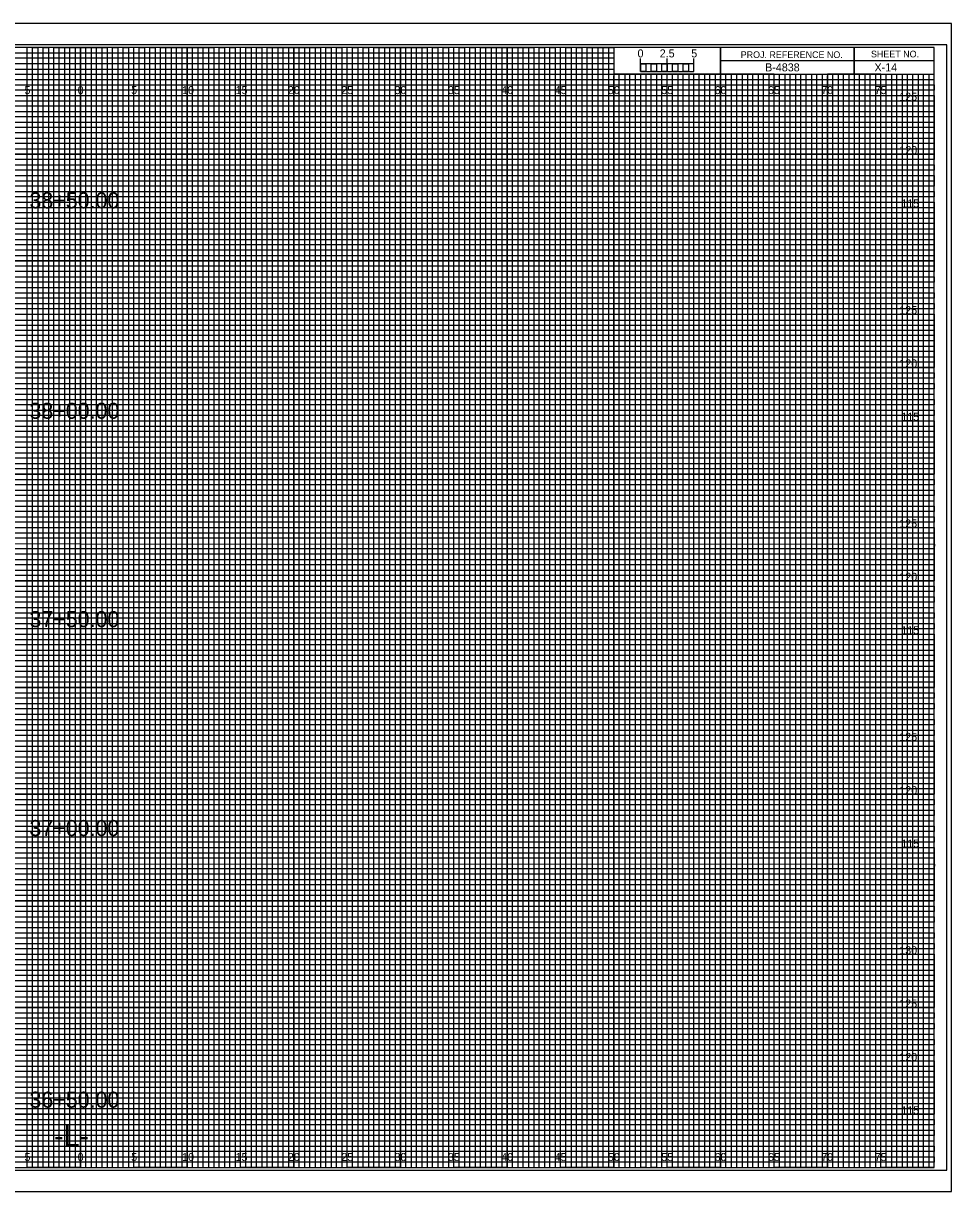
# Model space of a CAD drawing. Extents: x -7 to 182, y -2 to 1647.
# Drawn here: x 74.6 to 161.7, y 1317.8 to 1427.2 of the extents above; entities that cross this region are included whole.
import ezdxf

# ---------------------------------------------------------------- set-up
doc = ezdxf.new("R2010")
doc.units = 0
for name, color, linetype in [('Exist CMT Pavement', 7, 'Continuous'), ('Exist Cross Section Cell', 7, 'Continuous'), ('Exist XS Ground Line', 7, 'Continuous'), ('Prop CMT Pvmt Course 1', 7, 'Continuous'), ('Prop CMT Pvmt Course 2', 7, 'Continuous'), ('Prop CMT Pvmt Course 2 Wedge', 7, 'Continuous'), ('Prop CMT Pvmt Course 3', 7, 'Continuous'), ('Prop CMT Pvmt Surface', 7, 'Continuous'), ('Prop CMT Pvmt Surface Shoulder', 7, 'Continuous'), ('Prop CMT Pvmt Wedge Surface 1', 7, 'Continuous'), ('Prop CMT Pvmt Wedge Surface 2', 7, 'Continuous'), ('Prop CMT Pvmt Wedge Surface 3', 7, 'Continuous'), ('Prop CMT Shld Paved Course 1', 7, 'Continuous'), ('Prop CMT Shld Paved Course 2', 7, 'Continuous'), ('Prop CMT Shld Paved Course 3', 7, 'Continuous'), ('Prop CMT Slope Grass', 7, 'Continuous'), ('Prop CMT Subgrade Earthwork', 7, 'Continuous')]:
    doc.layers.add(name, color=color, linetype=linetype)

msp = doc.modelspace()

# ---------------------------------------------------------------- linework, layer by layer
at = {"layer": 'Exist XS Ground Line'}
for p, q in [((75, 1425), (70, 1425)), ((75, 1320), (75, 1425)), ((85, 1425), (80, 1425)), ((80, 1425), (80, 1320)), ((85, 1320), (85, 1425)), ((95, 1425), (90, 1425)), ((90, 1425), (90, 1320)), ((95, 1320), (95, 1425)), ((105, 1425), (100, 1425)), ((100, 1425), (100, 1320)), ((105, 1320), (105, 1425)), ((115, 1425), (110, 1425)), ((110, 1425), (110, 1320)), ((115, 1320), (115, 1425)), ((125, 1425), (120, 1425)), ((120, 1425), (120, 1320)), ((125, 1320), (125, 1425)), ((130, 1425), (130, 1320)), ((135, 1320), (135, 1422.5)), ((145, 1422.5), (140, 1422.5)), ((140, 1422.5), (140, 1320)), ((145, 1320), (145, 1422.5)), ((155, 1422.5), (150, 1422.5)), ((150, 1422.5), (150, 1320)), ((155, 1320), (155, 1422.5)), ((80, 1320), (75, 1320)), ((90, 1320), (85, 1320)), ((100, 1320), (95, 1320)), ((110, 1320), (105, 1320)), ((120, 1320), (115, 1320)), ((130, 1320), (125, 1320)), ((140, 1320), (135, 1320)), ((150, 1320), (145, 1320)), ((160, 1320), (155, 1320)), ((160, 1320), (160, 1320))]:
    msp.add_line(p, q, dxfattribs=at)
for points in [[(0, 1420), (160, 1420), (160, 1415), (0, 1415)], [(0, 1410), (160, 1410), (160, 1405), (0, 1405)], [(0, 1400), (160, 1400), (160, 1395), (0, 1395)], [(0, 1390), (160, 1390), (160, 1385), (0, 1385)], [(0, 1380), (160, 1380), (160, 1375), (0, 1375)], [(0, 1370), (160, 1370), (160, 1365), (0, 1365)], [(0, 1360), (160, 1360), (160, 1355), (0, 1355)], [(0, 1350), (160, 1350), (160, 1345), (0, 1345)], [(0, 1340), (160, 1340), (160, 1335), (0, 1335)], [(0, 1330), (160, 1330), (160, 1325), (0, 1325)]]:
    msp.add_lwpolyline(points, dxfattribs=at)
at = {"layer": 'Prop CMT Pvmt Course 2'}
for p, q in [((132.5, 1422.75), (132.5, 1423.95)), ((132.5, 1423.45), (132.5, 1423.95)), ((135, 1422.75), (135, 1423.95)), ((137.5, 1422.75), (137.5, 1423.95)), ((137.5, 1423.45), (137.5, 1423.95))]:
    msp.add_line(p, q, dxfattribs=at)
for points in [[(137.5, 1423.45), (132.5, 1423.45), (132.5, 1422.75), (137.5, 1422.75)], [(132.5, 1423.45), (133, 1423.45), (133, 1422.75), (132.5, 1422.75)], [(133.5, 1423.45), (134, 1423.45), (134, 1422.75), (133.5, 1422.75)], [(134.5, 1423.45), (135, 1423.45), (135, 1422.75), (134.5, 1422.75)], [(135.5, 1423.45), (136, 1423.45), (136, 1422.75), (135.5, 1422.75)], [(136.5, 1423.45), (137, 1423.45), (137, 1422.75), (136.5, 1422.75)]]:
    msp.add_lwpolyline(points, close=True, dxfattribs=at)
at = {"layer": 'Prop CMT Pvmt Course 3'}
msp.add_lwpolyline([(-6.7, 1317.75), (161.65, 1317.75), (161.65, 1427.25), (-6.7, 1427.25)], close=True, dxfattribs=at)
at = {"layer": 'Prop CMT Pvmt Wedge Surface 1'}
for p, q in [((0, 1424.5), (130, 1424.5)), ((130, 1423.99), (0, 1423.99)), ((0, 1423.5), (130, 1423.5)), ((130, 1424.5), (130, 1423.99)), ((130, 1423.5), (130, 1422.94)), ((130, 1422.94), (0, 1422.94)), ((0, 1422), (160, 1422))]:
    msp.add_line(p, q, dxfattribs=at)
for points in [[(0, 1421.5), (135, 1421.5), (160, 1421.5), (160, 1421), (0, 1421)], [(0, 1420.5), (160, 1420.5), (160, 1419.5), (0, 1419.5)], [(0, 1419), (160, 1419), (160, 1418.5), (0, 1418.49)], [(0, 1418), (160, 1418), (160, 1417), (0, 1417)], [(0, 1416.5), (160, 1416.5), (160, 1416), (0, 1416)], [(0, 1415.5), (160, 1415.5), (160, 1414.5), (0, 1414.5)], [(0, 1414), (160, 1414), (160, 1413.5), (0, 1413.5)], [(0, 1413), (160, 1413), (160, 1412), (0, 1412)], [(0, 1411.5), (160, 1411.5), (160, 1411), (0, 1411)], [(0, 1410.5), (160, 1410.5), (160, 1409.5), (0, 1409.5)], [(0, 1409), (160, 1409), (160, 1408.5), (0, 1408.5)], [(0, 1408), (160, 1408), (160, 1406.98), (160, 1406.5), (160, 1406), (0, 1406)], [(0, 1407), (160, 1407), (160, 1406.5), (0, 1406.5)], [(0, 1405.5), (160, 1405.5), (160, 1404.5), (0, 1404.52)], [(0, 1404.52), (160, 1404.5), (160, 1404), (0, 1404)], [(0, 1403.5), (160, 1403.5), (160, 1403), (0, 1403)], [(0, 1402), (160, 1402), (160, 1401.5), (0, 1401.5)], [(0, 1401), (160, 1401), (160, 1400.5), (0, 1400.5)], [(-0.04, 1399.44), (160, 1399.44), (160, 1398.94), (-0.04, 1398.94)], [(0, 1398.5), (160, 1398.5), (160, 1398), (0, 1398)], [(0, 1397), (160, 1397), (160, 1396.5), (0, 1396.5)], [(0, 1396), (160, 1396), (160, 1395.5), (0, 1395.5)], [(0, 1394.5), (160, 1394.5), (160, 1394), (0, 1394)], [(0, 1393.5), (160, 1393.5), (160, 1393), (0, 1393)], [(0, 1392), (160, 1392), (160, 1391.5), (0, 1391.5)], [(0, 1391), (160, 1391), (160, 1390.5), (0, 1390.5)], [(0, 1389.5), (160, 1389.5), (160, 1388.99), (0, 1389)], [(0, 1388.5), (160, 1388.5), (160, 1388), (0, 1388)], [(0, 1387), (160, 1387), (160, 1386.5), (0, 1386.5)], [(0, 1386), (160, 1386), (160, 1385.5), (0, 1385.5)], [(0, 1384.5), (160, 1384.5), (160, 1384), (0, 1384)], [(0, 1383.5), (160, 1383.5), (160, 1383), (0, 1383)], [(0, 1382), (160, 1382), (160, 1381.5), (0, 1381.5)], [(0, 1381), (160, 1381), (160, 1380.5), (0, 1380.5)], [(0, 1379.5), (160, 1379.5), (160, 1379), (0, 1379)], [(0, 1378.5), (160.03, 1378.45), (160, 1378), (0, 1378)], [(0, 1377), (160, 1377), (160, 1376.5), (0, 1376.5)], [(0, 1376), (160, 1376), (160, 1375.5), (0, 1375.5)], [(0, 1374.5), (160, 1374.5), (160, 1374), (0, 1374)], [(0, 1373.5), (160, 1373.5), (160, 1373), (0, 1373)], [(0, 1372), (160, 1372), (160, 1371.5), (0, 1371.5)], [(0, 1371), (160, 1371), (160, 1370.5), (0, 1370.5)], [(0, 1369.5), (160, 1369.5), (160, 1369), (0, 1369)], [(0, 1368.5), (160, 1368.5), (160, 1368), (0, 1368)], [(0, 1367), (160, 1367), (160, 1366.5), (0, 1366.5)], [(0, 1366), (160, 1366), (160, 1365.5), (0, 1365.5)], [(0, 1364.5), (160, 1364.5), (160, 1364), (0, 1364)], [(0, 1363.5), (160, 1363.5), (160, 1363), (0, 1363)], [(0, 1362), (160, 1362), (160, 1361.5), (0, 1361.5)], [(0, 1361), (160, 1361), (160, 1360.5), (0, 1360.5)], [(0, 1359.5), (160, 1359.5), (160, 1358.99), (0, 1359)], [(0, 1358.5), (160, 1358.5), (160, 1358), (0, 1358)], [(0, 1357), (160, 1357), (160, 1356.5), (0, 1356.5)], [(0, 1356), (160, 1356), (160, 1355.5), (0, 1355.5)], [(0, 1354.5), (160, 1354.5), (160, 1354), (0, 1354)], [(0, 1353.5), (160, 1353.5), (160, 1353), (0, 1353)], [(0, 1352), (160, 1352), (160, 1351.5), (0, 1351.5)], [(0, 1351), (160, 1351), (160, 1350.5), (0, 1350.5)], [(0, 1349.5), (160, 1349.5), (160, 1349), (0, 1349)], [(0, 1348.5), (160.03, 1348.45), (160, 1348), (0, 1348)], [(0, 1347), (160, 1347), (160, 1346.5), (0, 1346.5)], [(0, 1346), (160, 1346), (160, 1345.5), (0, 1345.5)], [(0, 1344.5), (160, 1344.5), (160, 1344), (0, 1344)], [(0, 1343.5), (160, 1343.5), (160, 1343), (0, 1343)], [(0, 1342), (160, 1342), (160, 1341.5), (0, 1341.5)], [(0, 1341), (160, 1341), (160, 1340.5), (0, 1340.5)], [(0, 1339.5), (160, 1339.5), (160, 1339), (0, 1339)], [(0, 1338.5), (160, 1338.5), (160, 1338), (0, 1338)], [(0, 1337), (160, 1337), (160, 1336.5), (0, 1336.5)], [(0, 1336), (160, 1336), (160, 1335.5), (0, 1335.5)], [(0, 1334.5), (160, 1334.5), (160, 1334), (0, 1334)], [(0, 1333.5), (160, 1333.5), (160, 1333), (0, 1333)], [(0, 1332), (160, 1332), (160, 1331.5), (0, 1331.5)], [(0, 1331), (160, 1331), (160, 1330.5), (0, 1330.5)], [(0, 1329.5), (160, 1329.5), (160, 1329), (0, 1329)], [(0, 1328.5), (160, 1328.5), (160, 1328), (0, 1328)], [(0, 1327), (160, 1327), (160, 1326.5), (0, 1326.5)], [(0, 1326), (160, 1326), (160, 1325.5), (0, 1325.5)], [(0, 1324.5), (160, 1324.5), (160, 1324), (0, 1324)], [(0, 1323.5), (160, 1323.5), (160, 1323), (0, 1323)], [(0, 1322), (160, 1322), (160, 1321.5), (0, 1321.5)], [(0, 1321), (160, 1321), (160, 1320.5), (0, 1320.5)]]:
    msp.add_lwpolyline(points, dxfattribs=at)
at = {"layer": 'Prop CMT Pvmt Wedge Surface 2'}
for p, q in [((152.5, 1425), (152.5, 1422.5)), ((152.5, 1422.5), (152.5, 1425)), ((160, 1423.75), (140, 1423.75)), ((140, 1423.75), (140, 1422.5)), ((140, 1422.5), (160, 1422.5))]:
    msp.add_line(p, q, dxfattribs=at)
for points in [[(160, 1425), (0, 1425), (0, 1320), (160, 1320)], [(140, 1425), (130, 1425), (130, 1422.52), (140, 1422.52)], [(160, 1425), (140, 1425), (140, 1422.5), (160, 1422.5)]]:
    msp.add_lwpolyline(points, close=True, dxfattribs=at)
at = {"layer": 'Prop CMT Pvmt Wedge Surface 3'}
for p, q in [((133.5, 1422.5), (133, 1422.5)), ((133, 1422.5), (133, 1320)), ((133.5, 1320), (133.5, 1422.5)), ((134.5, 1422.5), (134, 1422.5)), ((134, 1422.5), (134, 1320)), ((134.5, 1320), (134.5, 1422.5)), ((133, 1320), (132.5, 1320)), ((134, 1320), (133.5, 1320))]:
    msp.add_line(p, q, dxfattribs=at)
for points in [[(75, 1320), (75.5, 1320), (75.5, 1425), (76, 1425), (76, 1320)], [(76, 1320), (76.5, 1320), (76.5, 1425), (77, 1425), (77, 1320)], [(77.5, 1320), (78, 1320), (78, 1425), (78.5, 1425), (78.5, 1320)], [(78.5, 1320), (79, 1320), (79, 1425), (79.5, 1425), (79.5, 1320)], [(80, 1320), (80.5, 1320), (80.5, 1425), (81, 1425), (81, 1320)], [(81, 1320), (81.5, 1320), (81.5, 1425), (82, 1425), (82, 1320)], [(82.5, 1320), (83, 1320), (83, 1425), (83.5, 1425), (83.5, 1320)], [(83.5, 1320), (84, 1320), (84, 1425), (84.5, 1425), (84.5, 1320)], [(85, 1320), (85.5, 1320), (85.5, 1425), (86, 1425), (86, 1320)], [(86, 1320), (86.5, 1320), (86.5, 1425), (87, 1425), (87, 1320)], [(87.5, 1320), (88, 1320), (88, 1425), (88.5, 1425), (88.5, 1320)], [(88.5, 1320), (89, 1320), (89, 1425), (89.5, 1425), (89.5, 1320)], [(90, 1320), (90.5, 1320), (90.5, 1425), (91, 1425), (91, 1320)], [(91, 1320), (91.5, 1320), (91.5, 1425), (92, 1425), (92, 1320)], [(92.5, 1320), (93, 1320), (93, 1425), (93.5, 1425), (93.5, 1320)], [(93.5, 1320), (94, 1320), (94, 1425), (94.5, 1425), (94.5, 1320)], [(95, 1320), (95.5, 1320), (95.5, 1425), (96, 1425), (96, 1320)], [(96, 1320), (96.5, 1320), (96.5, 1425), (97, 1425), (97, 1320)], [(97.5, 1320), (98, 1320), (98, 1425), (98.5, 1425), (98.5, 1320)], [(98.5, 1320), (99, 1320), (99, 1425), (99.5, 1425), (99.5, 1320)], [(100, 1320), (100.5, 1320), (100.5, 1425), (101, 1425), (101, 1320)], [(101, 1320), (101.5, 1320), (101.5, 1425), (102, 1425), (102, 1320)], [(102.5, 1320), (103, 1320), (103, 1425), (103.5, 1425), (103.5, 1320)], [(103.5, 1320), (104, 1320), (104, 1425), (104.5, 1425), (104.5, 1320)], [(105, 1320), (105.5, 1320), (105.5, 1425), (106, 1425), (106, 1320)], [(106, 1320), (106.5, 1320), (106.5, 1425), (107, 1425), (107, 1320)], [(107.5, 1320), (108, 1320), (108, 1425), (108.5, 1425), (108.5, 1320)], [(108.5, 1320), (109, 1320), (109, 1425), (109.5, 1425), (109.5, 1320)], [(110, 1320), (110.5, 1320), (110.5, 1425), (111, 1425), (111, 1320)], [(111, 1320), (111.5, 1320), (111.5, 1425), (112, 1425), (112, 1320)], [(112.5, 1320), (113, 1320), (113, 1425), (113.5, 1425), (113.5, 1320)], [(113.5, 1320), (114, 1320), (114, 1425), (114.5, 1425), (114.5, 1320)], [(115, 1320), (115.5, 1320), (115.5, 1425), (116, 1425), (116, 1320)], [(116, 1320), (116.5, 1320), (116.5, 1425), (117, 1425), (117, 1320)], [(117.5, 1320), (118, 1320), (118, 1425), (118.5, 1425), (118.5, 1320)], [(118.5, 1320), (119, 1320), (119, 1425), (119.5, 1425), (119.5, 1320)], [(120, 1320), (120.5, 1320), (120.5, 1425), (121, 1425), (121, 1320)], [(121, 1320), (121.5, 1320), (121.5, 1425), (122, 1425), (122, 1320)], [(122.5, 1320), (123, 1320), (123, 1425), (123.5, 1425), (123.5, 1320)], [(123.5, 1320), (124, 1320), (124, 1425), (124.5, 1425), (124.5, 1320)], [(125, 1320), (125.5, 1320), (125.5, 1425), (126, 1425), (126, 1320)], [(126, 1320), (126.5, 1320), (126.5, 1425), (127, 1425), (127, 1320)], [(127.5, 1320), (128, 1320), (128, 1425), (128.5, 1425), (128.5, 1320)], [(128.5, 1320), (129, 1320), (129, 1425), (129.5, 1425), (129.5, 1320)], [(130, 1320), (130.5, 1320), (130.5, 1422.5), (131.01, 1422.5), (131.01, 1320)], [(131, 1320), (131.5, 1320), (131.5, 1422.5), (132, 1422.5), (132, 1320)], [(135, 1320), (135.49, 1320), (135.49, 1422.5), (136, 1422.5), (136, 1320)], [(136, 1320), (136.5, 1320), (136.5, 1422.5), (137.03, 1422.5), (137.03, 1320)], [(137.5, 1320), (138, 1320), (138, 1422.5), (138.5, 1422.5), (138.5, 1320)], [(138.5, 1320), (139, 1320), (139, 1422.5), (139.5, 1422.5), (139.5, 1320)], [(140, 1320), (140.5, 1320), (140.5, 1422.5), (141, 1422.5), (141, 1320)], [(141, 1320), (141.5, 1320), (141.5, 1422.5), (142, 1422.5), (142, 1320)], [(142.5, 1320), (143, 1320), (143, 1422.5), (143.5, 1422.5), (143.5, 1320)], [(143.5, 1320), (144, 1320), (144, 1422.5), (144.5, 1422.5), (144.5, 1320)], [(145, 1320), (145.5, 1320), (145.5, 1422.5), (146, 1422.5), (146, 1320)], [(146, 1320), (146.5, 1320), (146.5, 1422.5), (147, 1422.5), (147, 1320)], [(147.5, 1320), (148, 1320), (148, 1422.5), (148.5, 1422.5), (148.5, 1320)], [(148.5, 1320), (149, 1320), (149, 1422.5), (149.5, 1422.5), (149.5, 1320)], [(150, 1320), (150.5, 1320), (150.5, 1422.5), (151, 1422.5), (151, 1320)], [(151, 1320), (151.5, 1320), (151.5, 1422.5), (152, 1422.5), (152, 1320)], [(152.5, 1320), (153, 1320), (153, 1422.5), (153.5, 1422.5), (153.5, 1320)], [(153.5, 1320), (154, 1320), (154, 1422.5), (154.5, 1422.5), (154.5, 1320)], [(155, 1320), (155.5, 1320), (155.5, 1422.5), (156, 1422.5), (156, 1320)], [(156, 1320), (156.5, 1320), (156.5, 1422.5), (157, 1422.5), (157, 1320)], [(157.5, 1320), (158, 1320), (158, 1422.5), (158.5, 1422.5), (158.5, 1320)], [(158.5, 1320), (159, 1320), (159, 1422.5), (159.5, 1422.5), (159.5, 1320)]]:
    msp.add_lwpolyline(points, dxfattribs=at)
at = {"layer": 'Prop CMT Shld Paved Course 1'}
for p, q in [((75, 1320), (75, 1425)), ((80, 1320), (80, 1425)), ((85, 1320), (85, 1425)), ((90, 1320), (90, 1425)), ((95, 1320), (95, 1425)), ((100, 1320), (100, 1425)), ((105, 1320), (105, 1425)), ((110, 1320), (110, 1425)), ((115, 1320), (115, 1425)), ((120, 1320), (120, 1425)), ((125, 1320), (125, 1425)), ((130, 1320), (130, 1422.34)), ((135, 1320), (135, 1422.34)), ((140, 1320), (140, 1422.34)), ((145, 1320), (145, 1422.34)), ((150, 1320), (150, 1422.34)), ((155, 1320), (155, 1422.34)), ((0, 1420), (160, 1420)), ((0, 1415), (160, 1415)), ((0, 1410), (160, 1410)), ((0, 1405), (160, 1405)), ((0, 1400), (160, 1400)), ((0, 1395), (160, 1395)), ((0, 1390), (160, 1390)), ((0, 1385), (160, 1385)), ((0, 1380), (160, 1380)), ((0, 1375), (160, 1375)), ((0, 1370), (160, 1370)), ((0, 1365), (160, 1365)), ((0, 1360), (160, 1360)), ((0, 1355), (160, 1355)), ((0, 1350), (160, 1350)), ((0, 1345), (160, 1345)), ((0, 1340), (160, 1340)), ((0, 1335), (160, 1335)), ((0, 1330), (160, 1330)), ((0, 1325), (160, 1325))]:
    msp.add_line(p, q, dxfattribs=at)
at = {"layer": 'Prop CMT Shld Paved Course 2'}
for p, q in [((161.65, 1427.25), (-6.7, 1427.25)), ((-6.7, 1317.75), (161.65, 1317.75))]:
    msp.add_line(p, q, dxfattribs=at)
at = {"layer": 'Prop CMT Slope Grass'}
msp.add_lwpolyline([(-5.4, 1319.75), (161.2, 1319.75), (161.2, 1425.25), (-5.4, 1425.25)], close=True, dxfattribs=at)
at = {"layer": 'Prop CMT Subgrade Earthwork'}
for points in [[(72.5, 1320), (77.5, 1320), (77.5, 1425), (82.5, 1425), (82.5, 1320), (87.5, 1320), (87.5, 1425), (92.5, 1425), (92.5, 1320), (97.5, 1320), (97.5, 1425), (102.5, 1425), (102.5, 1320), (107.5, 1320), (107.5, 1425), (112.5, 1425), (112.5, 1320), (117.5, 1320), (117.5, 1425), (122.5, 1425), (122.5, 1320), (127.5, 1320), (127.5, 1425), (129.97, 1425), (130, 1425), (130, 1422.5), (132.5, 1422.5), (132.5, 1320), (137.5, 1320), (137.5, 1422.5), (142.5, 1422.5), (142.5, 1320), (147.5, 1320), (147.5, 1422.5), (152.5, 1422.5), (152.5, 1320), (157.5, 1320), (157.5, 1422.5)], [(0, 1422.5), (137.5, 1422.5)], [(0, 1412.5), (160, 1412.5), (160, 1417.5), (0, 1417.5)], [(0, 1402.5), (160, 1402.5), (160, 1407.5), (0, 1407.5)], [(0, 1392.5), (160, 1392.5), (160, 1397.5), (0, 1397.5)], [(0, 1382.5), (160, 1382.5), (160, 1387.5), (0, 1387.5)], [(0, 1372.5), (160, 1372.5), (160, 1377.5), (0, 1377.5)], [(0, 1362.5), (160, 1362.5), (160, 1367.5), (0, 1367.5)], [(0, 1352.5), (160, 1352.5), (160, 1357.5), (0, 1357.5)], [(0, 1342.5), (160, 1342.5), (160, 1347.5), (0, 1347.5)], [(0, 1332.5), (160, 1332.5), (160, 1337.5), (0, 1337.5)], [(0, 1322.5), (160, 1322.5), (160, 1327.5), (0, 1327.5)]]:
    msp.add_lwpolyline(points, dxfattribs=at)

# ---------------------------------------------------------------- texts
at = {"layer": 'Exist CMT Pavement'}
for s, p in [('38+50.00', (75.21, 1409.91)), ('38+00.00', (75.21, 1390.19)), ('37+50.00', (75.21, 1370.66)), ('37+00.00', (75.21, 1351.08)), ('36+50.00', (75.21, 1325.62))]:
    msp.add_text(s, height=1.5, dxfattribs=at).set_placement(p)
at = {"layer": 'Exist Cross Section Cell'}
for s, p in [('5', (74.74, 1420.62)), ('0', (79.73, 1420.62)), ('0', (79.73, 1420.62)), ('5', (84.74, 1420.62)), ('10', (89.52, 1420.62)), ('15', (94.53, 1420.62)), ('20', (99.43, 1420.62)), ('25', (104.44, 1420.62)), ('30', (109.43, 1420.62)), ('35', (114.44, 1420.62)), ('40', (119.43, 1420.62)), ('45', (124.44, 1420.62)), ('50', (129.43, 1420.62)), ('55', (134.44, 1420.62)), ('60', (139.43, 1420.62)), ('65', (144.44, 1420.62)), ('70', (149.43, 1420.62)), ('75', (154.44, 1420.62)), ('5', (74.74, 1320.62)), ('0', (79.73, 1320.62)), ('0', (79.73, 1320.62)), ('5', (84.74, 1320.62)), ('10', (89.52, 1320.62)), ('15', (94.53, 1320.62)), ('20', (99.43, 1320.62)), ('25', (104.44, 1320.62)), ('30', (109.43, 1320.62)), ('35', (114.44, 1320.62)), ('40', (119.43, 1320.62)), ('45', (124.44, 1320.62)), ('50', (129.43, 1320.62)), ('55', (134.44, 1320.62)), ('60', (139.43, 1320.62)), ('65', (144.44, 1320.62)), ('70', (149.43, 1320.62)), ('75', (154.44, 1320.62))]:
    msp.add_text(s, height=0.75, dxfattribs=at).set_placement(p)
at = {"layer": 'Prop CMT Pvmt Course 1'}
msp.add_text('-L-', height=2, dxfattribs=at).set_placement((77.53, 1322))
at = {"layer": 'Prop CMT Pvmt Course 2'}
msp.add_text('0', height=0.75, dxfattribs=at).set_placement((132.21, 1424.06))
at = {"layer": 'Prop CMT Pvmt Course 2 Wedge'}
for s, p in [('2.5', (134.29, 1424.06)), ('5', (137.24, 1424.06))]:
    msp.add_text(s, height=0.75, dxfattribs=at).set_placement(p)
at = {"layer": 'Prop CMT Pvmt Surface'}
msp.add_text('X-14', height=0.75, dxfattribs=at).set_placement((154.42, 1422.75))
at = {"layer": 'Prop CMT Pvmt Surface Shoulder'}
msp.add_text('B-4838', height=0.75, dxfattribs=at).set_placement((144.17, 1422.75))
at = {"layer": 'Prop CMT Pvmt Wedge Surface 2'}
for s, p in [('PROJ. REFERENCE NO.', (141.88, 1424)), ('SHEET NO.', (154.09, 1424.06))]:
    msp.add_text(s, height=0.625, dxfattribs=at).set_placement(p)
at = {"layer": 'Prop CMT Shld Paved Course 3'}
for s, p in [('125', (156.74, 1420)), ('120', (156.75, 1415)), ('115', (156.93, 1410)), ('125', (156.74, 1400)), ('120', (156.75, 1395)), ('115', (156.93, 1390)), ('125', (156.74, 1380)), ('120', (156.75, 1375)), ('115', (156.93, 1370)), ('125', (156.74, 1360)), ('120', (156.75, 1355)), ('115', (156.93, 1350)), ('130', (156.74, 1340)), ('125', (156.74, 1335)), ('120', (156.75, 1330)), ('115', (156.93, 1325))]:
    msp.add_text(s, height=0.75, dxfattribs=at).set_placement(p)

doc.saveas('drawing.dxf')
